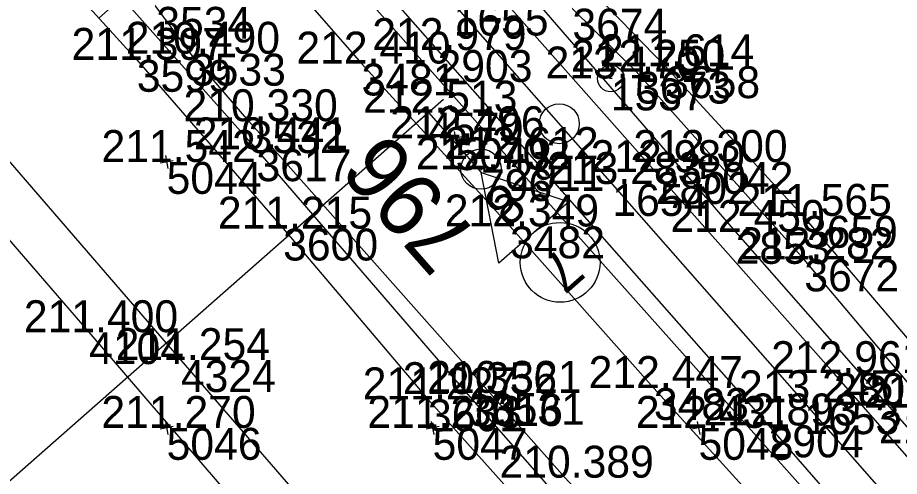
# Model space of a CAD drawing. Extents: x -556590 to -554855, y -1137918 to -1135717.
# Drawn here: x -555585.6 to -555552.45, y -1136561.82 to -1136544.57 of the extents above; entities that cross this region are included whole.
import ezdxf

# ---------------------------------------------------------------- set-up
doc = ezdxf.new("R2010")
doc.units = 0
for name, color, linetype in [('Vrstva 1', 7, 'Continuous'), ('Vrstva 4', 7, 'Continuous'), ('Vrstva 48', 7, 'Continuous'), ('Vrstva 49', 7, 'Continuous'), ('Vrstva 5', 7, 'Continuous'), ('Vrstva 51', 7, 'Continuous'), ('Vrstva 60', 7, 'Continuous'), ('Vrstva 61', 7, 'Continuous'), ('Vrstva 63', 7, 'Continuous'), ('Vrstva 7', 7, 'Continuous')]:
    doc.layers.add(name, color=color, linetype=linetype)

msp = doc.modelspace()

# ---------------------------------------------------------------- linework, layer by layer
at = {"layer": 'Vrstva 1'}
msp.add_lwpolyline([(-555484.828, -1136640.001), (-555491.528, -1136632.383), (-555498.412, -1136624.55), (-555504.946, -1136617.11), (-555511.606, -1136609.535), (-555518.452, -1136601.747), (-555525.811, -1136593.383), (-555532.445, -1136585.842), (-555538.802, -1136578.615), (-555545.375, -1136571.148), (-555549.372, -1136566.6), (-555556.022, -1136559.036), (-555563.24, -1136550.829), (-555569.21, -1136544.044), (-555575.755, -1136536.598), (-555582.668, -1136528.735), (-555589.184, -1136521.331), (-555595.934, -1136513.658), (-555603.173, -1136505.431), (-555609.997, -1136497.674), (-555617.047, -1136489.655), (-555624.151, -1136481.584)], dxfattribs=at)
at = {"layer": 'Vrstva 4'}
for points in [[(-555633.977, -1136472.931), (-555622.465, -1136485.967), (-555610.794, -1136499.26), (-555598.984, -1136512.703), (-555590.536, -1136522.311), (-555579.049, -1136535.308), (-555569.813, -1136545.791), (-555557.364, -1136559.907), (-555552.619, -1136565.36), (-555551.747, -1136566.427), (-555551.548, -1136566.959), (-555551.515, -1136567.335), (-555551.578, -1136567.564), (-555554.515, -1136564.027), (-555567.11, -1136549.89), (-555580.384, -1136534.938), (-555595.88, -1136517.383), (-555608.088, -1136503.55), (-555622.431, -1136487.275), (-555632.955, -1136475.376)], [(-555527.948, -1136588.271), (-555529.845, -1136586.468), (-555535.205, -1136580.281), (-555544.634, -1136569.624), (-555554.912, -1136557.94), (-555561.607, -1136550.38), (-555568.587, -1136542.487), (-555575.122, -1136534.99), (-555586.388, -1136522.085), (-555596.442, -1136510.594), (-555607.811, -1136497.74), (-555613.591, -1136490.916), (-555614.188, -1136490.137), (-555614.496, -1136489.875), (-555614.865, -1136489.81), (-555615.227, -1136489.544), (-555615.638, -1136488.973), (-555615.944, -1136488.425), (-555617.216, -1136486.813), (-555618.033, -1136485.9), (-555620.12, -1136483.808), (-555629.064, -1136473.626)], [(-555620.889, -1136481.776), (-555617.266, -1136485.877), (-555616.608, -1136486.727), (-555616.229, -1136487.35), (-555615.754, -1136488.048), (-555614.935, -1136489.158), (-555614.508, -1136489.453), (-555614.14, -1136489.564), (-555613.829, -1136489.72), (-555613.471, -1136490.05), (-555612.691, -1136491.001), (-555601.238, -1136504.064), (-555594.724, -1136511.412), (-555586.133, -1136521.236), (-555576.395, -1136532.26), (-555571.093, -1136538.752), (-555569.249, -1136540.97), (-555569.022, -1136541.086), (-555568.815, -1136541.122), (-555568.544, -1136541.236), (-555568.212, -1136541.515), (-555567.584, -1136542.237), (-555558.604, -1136552.63), (-555548.815, -1136563.777)]]:
    msp.add_lwpolyline(points, dxfattribs=at)
at = {"layer": 'Vrstva 48'}
msp.add_line((-555582.546, -1136544.588), (-555581.689, -1136543.81), dxfattribs=at)
at = {"layer": 'Vrstva 49'}
for p, q in [((-555568.892, -1136549.059), (-555569.384, -1136549.153)), ((-555569.185, -1136548.86), (-555569.091, -1136549.352)), ((-555580.047, -1136549.754), (-555579.953, -1136550.246)), ((-555560.047, -1136549.754), (-555559.953, -1136550.246)), ((-555579.754, -1136549.953), (-555580.246, -1136550.047)), ((-555559.754, -1136549.953), (-555560.246, -1136550.047)), ((-555580.047, -1136559.754), (-555579.953, -1136560.246)), ((-555570.047, -1136559.754), (-555569.953, -1136560.246)), ((-555560.047, -1136559.754), (-555559.953, -1136560.246)), ((-555579.754, -1136559.953), (-555580.246, -1136560.047)), ((-555569.754, -1136559.953), (-555570.246, -1136560.047)), ((-555559.754, -1136559.953), (-555560.246, -1136560.047))]:
    msp.add_line(p, q, dxfattribs=at)
for points in [[(-555544.441, -1136566.85), (-555551.334, -1136559.234), (-555556.022, -1136553.665), (-555562.345, -1136546.603), (-555564.741, -1136544.236), (-555565.657, -1136543.328), (-555566.361, -1136542.353), (-555566.72, -1136541.407), (-555567.2, -1136540.125), (-555568.614, -1136537.846), (-555569.574, -1136536.763), (-555570.701, -1136536.259), (-555572.258, -1136535.035), (-555574.629, -1136532.477), (-555578.984, -1136527.537), (-555585.28, -1136520.429), (-555592.352, -1136512.399), (-555598.214, -1136505.509), (-555604.763, -1136498.037), (-555612.017, -1136489.54), (-555614.371, -1136486.921), (-555618.587, -1136482.137)], [(-555616.367, -1136483.595), (-555611.354, -1136489.14), (-555606.835, -1136494.271), (-555598.938, -1136503.31), (-555592.939, -1136510.075), (-555586.393, -1136517.565), (-555578.721, -1136526.276), (-555572.465, -1136533.43), (-555570.363, -1136535.704), (-555569.422, -1136536.555), (-555568.805, -1136537.164), (-555568.091, -1136537.936), (-555566.767, -1136539.559), (-555565.5, -1136541.619), (-555564.932, -1136542.574), (-555564.199, -1136543.353), (-555561.254, -1136546.4), (-555556.075, -1136552.026), (-555549.532, -1136559.703), (-555541.621, -1136568.507), (-555533.546, -1136577.461), (-555526.5, -1136585.626), (-555524.905, -1136587.515), (-555523.504, -1136589.317)], [(-555628.42, -1136484.274), (-555623.94, -1136489.1), (-555619.314, -1136494.5), (-555613.741, -1136500.597), (-555608.518, -1136505.891), (-555604.409, -1136510.119), (-555599.875, -1136515.161), (-555595.41, -1136520.619), (-555589.566, -1136527.288), (-555582.946, -1136535.025), (-555577.167, -1136541.145), (-555572.67, -1136546.299), (-555567.086, -1136552.424), (-555561.678, -1136558.501), (-555555.26, -1136565.576), (-555550.895, -1136570.322), (-555544.6, -1136577.353), (-555537.567, -1136585.475), (-555533.617, -1136590.772), (-555528.815, -1136596.499), (-555522.487, -1136603.401), (-555516.942, -1136609.447), (-555511.773, -1136615.038)], [(-555627.575, -1136492.996), (-555620.189, -1136501.785), (-555614.395, -1136507.641), (-555608.207, -1136514.983), (-555604.077, -1136519.626), (-555597.222, -1136527.781), (-555590.603, -1136535.223), (-555585.578, -1136541.245), (-555581.121, -1136546.159), (-555575.618, -1136552.505), (-555570.174, -1136558.926), (-555563.045, -1136566.888), (-555556.383, -1136574.459), (-555549.185, -1136582.65), (-555544.079, -1136588.943), (-555541.134, -1136592.046), (-555539.258, -1136593.394), (-555537.771, -1136594.285), (-555536.849, -1136594.715)], [(-555536.849, -1136594.715), (-555540.376, -1136591.287), (-555542.304, -1136589.532), (-555545.275, -1136585.728), (-555550.552, -1136579.476), (-555554.891, -1136574.523), (-555562.014, -1136566.318), (-555568.67, -1136558.73), (-555576.622, -1136549.522), (-555583.828, -1136541.398), (-555590.24, -1136533.975), (-555598.085, -1136525.186), (-555605.251, -1136517.073), (-555613.661, -1136507.135), (-555619.626, -1136500.541), (-555625.788, -1136493.44)], [(-555486.964, -1136647.08), (-555497.695, -1136635.474), (-555512.132, -1136619.842), (-555517.928, -1136612.023), (-555527.868, -1136602.65), (-555533.627, -1136596.699), (-555540.742, -1136588.651), (-555547.888, -1136580.93), (-555554.52, -1136574.067), (-555558.139, -1136569.934), (-555559.459, -1136567.885), (-555565.029, -1136561.871), (-555567.843, -1136558.682), (-555576.914, -1136548.466), (-555579.087, -1136545.929), (-555580.389, -1136544.168), (-555583.887, -1136540.023), (-555589.126, -1136533.954), (-555597.059, -1136524.316), (-555605.037, -1136516.249), (-555608.96, -1136511.073), (-555615.08, -1136504.35), (-555624.636, -1136493.356)]]:
    msp.add_lwpolyline(points, dxfattribs=at)
at = {"layer": 'Vrstva 5'}
for p, q in [((-555569.595, -1136547.65), (-555570.721, -1136548.64)), ((-555570.158, -1136548.145), (-555615.203, -1136587.78))]:
    msp.add_line(p, q, dxfattribs=at)
msp.add_lwpolyline([(-555570.158, -1136548.145), (-555568.176, -1136550.397), (-555564.881, -1136551.494), (-555567.508, -1136553.806), (-555568.176, -1136550.397)], dxfattribs=at)
msp.add_circle((-555565.204, -1136553.776), 1.5, dxfattribs=at)
at = {"layer": 'Vrstva 51'}
for points in [[(-555743.133, -1136368.314), (-555733.406, -1136379.475), (-555727.162, -1136386.762), (-555718.214, -1136397.183), (-555709.998, -1136406.534), (-555700.89, -1136417.124), (-555690.385, -1136429.309), (-555680.58, -1136440.643), (-555668.402, -1136454.771), (-555656.288, -1136468.58), (-555643.895, -1136482.917), (-555632.798, -1136495.751), (-555617.483, -1136513.593), (-555605.979, -1136526.789), (-555593.57, -1136541.12), (-555579.464, -1136557.45), (-555567.58, -1136571.183), (-555555.68, -1136584.796), (-555545.666, -1136596.303), (-555537.365, -1136605.817), (-555530.457, -1136613.715), (-555520.191, -1136625.354), (-555507.504, -1136639.736)], [(-555505.522, -1136644.883), (-555519.562, -1136629.073), (-555531.744, -1136615.155), (-555540.175, -1136605.5), (-555547.673, -1136596.899), (-555556.471, -1136586.787), (-555567.721, -1136573.974), (-555575.942, -1136564.513), (-555582.917, -1136556.401), (-555594.357, -1136543.153), (-555603.925, -1136532.234), (-555617.682, -1136516.291), (-555630.463, -1136501.491), (-555643.583, -1136486.305), (-555657.513, -1136470.232), (-555666.727, -1136459.683), (-555678.561, -1136446.033), (-555691.372, -1136431.214), (-555703.054, -1136417.695), (-555713.773, -1136405.268), (-555725.819, -1136391.439), (-555738.306, -1136376.946), (-555744.231, -1136369.998)]]:
    msp.add_lwpolyline(points, dxfattribs=at)
at = {"layer": 'Vrstva 60'}
for p, q in [((-555569.813, -1136545.791), (-555569.813, -1136545.791)), ((-555581.121, -1136546.159), (-555581.121, -1136546.159)), ((-555579.087, -1136545.929), (-555579.087, -1136545.929)), ((-555572.67, -1136546.299), (-555572.67, -1136546.299)), ((-555561.254, -1136546.4), (-555561.254, -1136546.4)), ((-555562.345, -1136546.603), (-555562.345, -1136546.603)), ((-555563.3, -1136546.86), (-555563.3, -1136546.86)), ((-555570.158, -1136548.145), (-555570.158, -1136548.145)), ((-555576.914, -1136548.466), (-555576.914, -1136548.466)), ((-555569.138, -1136549.106), (-555569.138, -1136549.106)), ((-555576.622, -1136549.522), (-555576.622, -1136549.522)), ((-555580, -1136550), (-555580, -1136550)), ((-555567.11, -1136549.89), (-555567.11, -1136549.89)), ((-555560, -1136550), (-555560, -1136550)), ((-555568.179, -1136550.271), (-555568.179, -1136550.271)), ((-555561.607, -1136550.38), (-555561.607, -1136550.38)), ((-555563.24, -1136550.829), (-555563.24, -1136550.829)), ((-555556.075, -1136552.026), (-555556.075, -1136552.026)), ((-555567.086, -1136552.424), (-555567.086, -1136552.424)), ((-555575.618, -1136552.505), (-555575.618, -1136552.505)), ((-555558.604, -1136552.63), (-555558.604, -1136552.63)), ((-555556.022, -1136553.665), (-555556.022, -1136553.665)), ((-555582.917, -1136556.401), (-555582.917, -1136556.401)), ((-555579.464, -1136557.45), (-555579.464, -1136557.45)), ((-555554.912, -1136557.94), (-555554.912, -1136557.94)), ((-555568.67, -1136558.73), (-555568.67, -1136558.73)), ((-555567.843, -1136558.682), (-555567.843, -1136558.682)), ((-555561.678, -1136558.501), (-555561.678, -1136558.501)), ((-555570.174, -1136558.926), (-555570.174, -1136558.926)), ((-555556.022, -1136559.036), (-555556.022, -1136559.036)), ((-555580, -1136560), (-555580, -1136560)), ((-555570, -1136560), (-555570, -1136560)), ((-555560, -1136560), (-555560, -1136560)), ((-555557.364, -1136559.907), (-555557.364, -1136559.907))]:
    msp.add_line(p, q, dxfattribs=at)
at = {"layer": 'Vrstva 63'}
msp.add_line((-555568.146, -1136550.309), (-555568.212, -1136550.233), dxfattribs=at)
msp.add_circle((-555568.179, -1136550.271), 0.756, dxfattribs=at)
at = {"layer": 'Vrstva 7'}
msp.add_line((-555563.25, -1136546.86), (-555563.35, -1136546.86), dxfattribs=at)
for centre, radius in [((-555563.3, -1136546.86), 0.5), ((-555565.235, -1136548.562), 0.75)]:
    msp.add_circle(centre, radius, dxfattribs=at)

# ---------------------------------------------------------------- texts
at = {"layer": 'Vrstva 5'}
for s, p in [('8', (-555567.351, -1136550.67)), ('7', (-555565.173, -1136553.149))]:
    msp.add_text(s, height=1.5, rotation=221.344, dxfattribs=at).set_placement(p)
at = {"layer": 'Vrstva 60'}
for s, p in [('3534', (-555580.389, -1136545.368)), ('1655', (-555569.21, -1136545.244)), ('3674', (-555564.741, -1136545.436)), ('2903', (-555569.813, -1136546.991)), ('3599', (-555581.121, -1136547.359)), ('3533', (-555579.087, -1136547.129)), ('3481', (-555572.67, -1136547.499)), ('3658', (-555561.254, -1136547.6)), ('3673', (-555562.345, -1136547.803)), ('1537', (-555563.3, -1136548.06)), ('4570', (-555570.158, -1136549.345)), ('3532', (-555576.914, -1136549.666)), ('5043', (-555569.138, -1136550.306)), ('3617', (-555576.622, -1136550.722)), ('5044', (-555580, -1136551.2)), ('2911', (-555567.11, -1136551.09)), ('5042', (-555560, -1136551.2)), ('796', (-555568.179, -1136551.471)), ('2802', (-555561.607, -1136551.58)), ('1654', (-555563.24, -1136552.029)), ('3659', (-555556.075, -1136553.226)), ('3482', (-555567.086, -1136553.624)), ('3600', (-555575.618, -1136553.705)), ('2853', (-555558.604, -1136553.83)), ('3672', (-555556.022, -1136554.865)), ('4104', (-555582.917, -1136557.601)), ('4324', (-555579.464, -1136558.65)), ('2801', (-555554.912, -1136559.14)), ('3616', (-555568.67, -1136559.93)), ('3531', (-555567.843, -1136559.882)), ('3483', (-555561.678, -1136559.701)), ('3601', (-555570.174, -1136560.126)), ('1653', (-555556.022, -1136560.236)), ('5046', (-555580, -1136561.2)), ('5047', (-555570, -1136561.2)), ('5048', (-555560, -1136561.2)), ('2904', (-555557.364, -1136561.107))]:
    msp.add_text(s, height=1.2, dxfattribs=at).set_placement(p)
at = {"layer": 'Vrstva 61'}
for s, p in [('210.490', (-555581.538, -1136545.929)), ('212.979', (-555572.267, -1136545.791)), ('211.397', (-555583.573, -1136546.159)), ('212.410', (-555575.121, -1136546.299)), ('212.250', (-555564.796, -1136546.603)), ('211.614', (-555563.705, -1136546.4)), ('213.170', (-555565.751, -1136546.86)), ('212.513', (-555572.61, -1136548.145)), ('210.330', (-555579.365, -1136548.466)), ('212.496', (-555571.59, -1136549.106)), ('210.441', (-555578.979, -1136549.522)), ('211.542', (-555582.448, -1136550)), ('212.612', (-555569.558, -1136549.89)), ('212.300', (-555562.451, -1136550)), ('212.702', (-555570.627, -1136550.271)), ('212.980', (-555564.058, -1136550.38)), ('213.283', (-555565.692, -1136550.829)), ('211.565', (-555558.531, -1136552.026)), ('211.215', (-555578.074, -1136552.505)), ('212.349', (-555569.54, -1136552.424)), ('212.450', (-555561.055, -1136552.63)), ('212.282', (-555558.47, -1136553.665)), ('211.400', (-555585.368, -1136556.401)), ('211.254', (-555581.915, -1136557.45)), ('212.961', (-555557.269, -1136557.94)), ('212.447', (-555564.13, -1136558.501)), ('211.227', (-555572.626, -1136558.926)), ('210.356', (-555571.122, -1136558.73)), ('210.321', (-555570.2, -1136558.682)), ('213.245', (-555558.478, -1136559.036)), ('212.209', (-555553.788, -1136559.234)), ('212.893', (-555559.816, -1136559.907)), ('211.270', (-555582.451, -1136560)), ('211.233', (-555572.452, -1136560)), ('212.431', (-555562.357, -1136560)), ('212.393', (-555553.219, -1136560.576)), ('210.389', (-555567.483, -1136561.871))]:
    msp.add_text(s, height=1.2, dxfattribs=at).set_placement(p)
at = {"layer": 'Vrstva 63'}
msp.add_text('796', height=2.4, rotation=131.344, dxfattribs=at).set_placement((-555568.197, -1136552.815))

doc.saveas('drawing.dxf')
